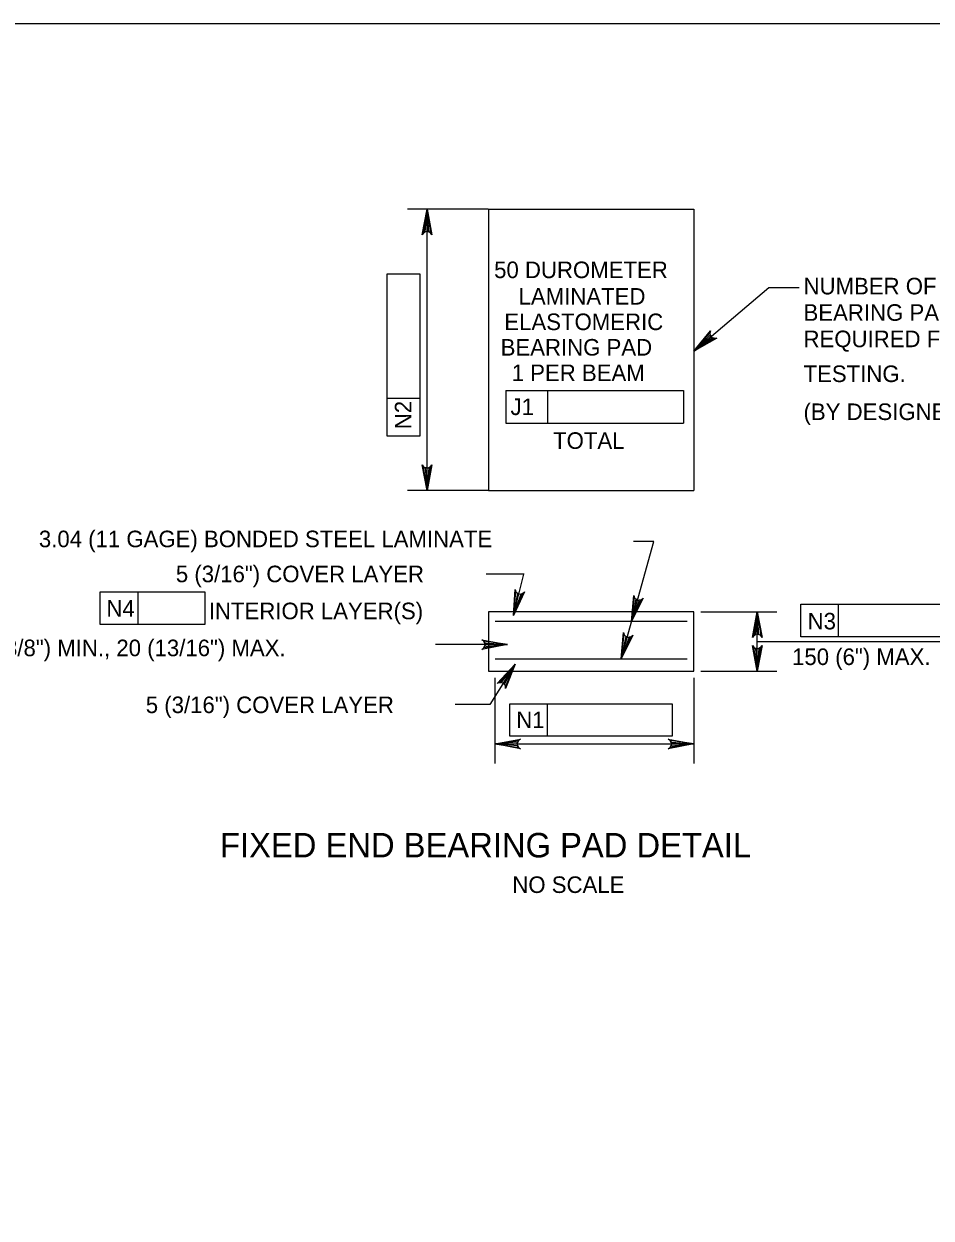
# Model space of a CAD drawing. Extents: x -13 to 81, y -176 to 0.
# Drawn here: x 52.67 to 59.23, y -31.4 to -22.75 of the extents above; entities that cross this region are included whole.
import ezdxf

# ---------------------------------------------------------------- set-up
doc = ezdxf.new("R2010")
doc.units = 0
for name, color, linetype in [('Level 1', 7, 'Continuous'), ('Level 3', 7, 'Continuous'), ('Level 5', 7, 'Continuous'), ('Level 6', 7, 'Continuous'), ('Level 8', 7, 'Continuous')]:
    doc.layers.add(name, color=color, linetype=linetype)

msp = doc.modelspace()

# ---------------------------------------------------------------- linework, layer by layer
at = {"layer": 'Level 1'}
msp.add_lwpolyline([(35.75, -43.25), (67.25, -43.25), (67.25, -22.75), (35.75, -22.75)], close=True, dxfattribs=at)
at = {"layer": 'Level 3'}
for p, q in [((55.5849, -26.1297), (55.5849, -24.0916)), ((56.029, -24.0916), (57.5171, -24.0916)), ((56.029, -24.0916), (56.029, -26.1297)), ((57.5171, -24.0916), (57.5171, -26.1297)), ((55.2975, -24.5611), (55.5337, -24.5611)), ((55.2975, -25.4631), (55.2975, -24.5611)), ((55.5337, -24.5611), (55.5337, -25.7369)), ((58.0596, -24.6599), (58.2797, -24.6599)), ((56.1547, -25.4057), (56.4571, -25.4057)), ((56.1547, -25.4057), (56.1547, -25.6419)), ((56.4571, -25.4057), (56.4571, -25.6419)), ((56.4571, -25.4057), (57.4407, -25.4057)), ((57.4407, -25.4057), (57.4407, -25.6419)), ((55.2975, -25.7369), (55.2975, -25.4631)), ((55.5337, -25.4631), (55.2975, -25.4631)), ((56.1547, -25.6419), (57.4407, -25.6419)), ((55.5337, -25.7369), (55.2975, -25.7369)), ((56.029, -26.1297), (57.5171, -26.1297)), ((56.2869, -26.7374), (56.0134, -26.7374)), ((56.2097, -27.037), (56.2868, -26.7373)), ((53.2192, -27.1005), (53.2192, -26.8643)), ((53.2192, -26.8643), (53.9756, -26.8643)), ((53.493, -27.1005), (53.493, -26.8643)), ((53.9756, -26.8643), (53.9756, -27.1005)), ((58.2901, -26.9548), (58.5639, -26.9548)), ((58.2901, -27.1909), (58.2901, -26.9548)), ((58.5639, -27.1909), (58.5639, -26.9548)), ((58.5639, -26.9548), (59.4659, -26.9548)), ((57.5171, -27.0092), (56.029, -27.0092)), ((56.029, -27.0092), (56.029, -27.4384)), ((57.5171, -27.4384), (57.5171, -27.0092)), ((57.5662, -27.0092), (58.1169, -27.0092)), ((57.9752, -27.4384), (57.9752, -27.0092)), ((57.9752, -27.0092), (57.9752, -27.0092)), ((53.9756, -27.1005), (53.2192, -27.1005)), ((57.4671, -27.0803), (56.079, -27.0803)), ((57.9752, -27.2237), (59.4815, -27.2237)), ((59.4659, -27.1909), (58.2901, -27.1909)), ((56.2222, -27.3879), (56.0384, -27.6814)), ((56.079, -27.349), (57.4671, -27.349)), ((56.029, -27.4384), (57.5171, -27.4384)), ((57.5662, -27.4384), (58.1169, -27.4384)), ((56.0384, -27.6814), (55.7892, -27.6814)), ((56.1831, -27.6747), (56.4569, -27.6747)), ((56.1831, -27.911), (56.1831, -27.6747)), ((56.4569, -27.911), (56.4569, -27.6747)), ((56.4569, -27.6747), (57.3588, -27.6747)), ((57.3588, -27.6747), (57.3588, -27.911)), ((57.3588, -27.911), (56.1831, -27.911))]:
    msp.add_line(p, q, dxfattribs=at)
for points in [[(55.5849, -24.0916), (55.6198, -24.278), (55.6099, -24.2637), (55.5974, -24.2562), (55.5849, -24.2541), (55.5724, -24.2562), (55.5599, -24.2637), (55.55, -24.278), (55.5849, -24.0916), (55.5599, -24.2637), (55.5724, -24.2562), (55.5849, -24.0916), (55.5849, -24.2541), (55.5974, -24.2562), (55.5849, -24.0916), (55.6099, -24.2637)], [(57.5171, -25.1202), (58.0596, -24.6598)], [(57.5171, -25.1202), (57.6366, -24.9729), (57.6321, -24.9898), (57.6345, -25.0041), (57.641, -25.015), (57.6507, -25.0232), (57.6644, -25.0279), (57.6818, -25.0262), (57.5171, -25.1202), (57.6644, -25.0279), (57.6507, -25.0232), (57.5171, -25.1202), (57.641, -25.015), (57.6345, -25.0041), (57.5171, -25.1202), (57.6321, -24.9898)], [(55.5849, -26.1297), (55.55, -25.9433), (55.5599, -25.9577), (55.5724, -25.9651), (55.5849, -25.9672), (55.5974, -25.9651), (55.6099, -25.9577), (55.6198, -25.9433), (55.5849, -26.1297), (55.6099, -25.9577), (55.5974, -25.9651), (55.5849, -26.1297), (55.5849, -25.9672), (55.5724, -25.9651), (55.5849, -26.1297), (55.5599, -25.9577)], [(56.2097, -27.037), (56.2223, -26.8477), (56.2284, -26.8642), (56.2387, -26.8744), (56.2503, -26.8796), (56.2628, -26.8807), (56.2768, -26.8766), (56.29, -26.8652), (56.2097, -27.037), (56.2768, -26.8766), (56.2628, -26.8807), (56.2097, -27.037), (56.2503, -26.8796), (56.2387, -26.8744), (56.2097, -27.037), (56.2284, -26.8642)], [(57.0656, -27.0803), (57.0816, -26.8913), (57.0873, -26.9078), (57.0974, -26.9183), (57.1089, -26.9237), (57.1215, -26.925), (57.1355, -26.9212), (57.1489, -26.91), (57.0656, -27.0803), (57.1355, -26.9212), (57.1215, -26.925), (57.0656, -27.0803), (57.1089, -26.9237), (57.0974, -26.9183), (57.0656, -27.0803), (57.0873, -26.9078)], [(57.9752, -27.0092), (58.0102, -27.1956), (58.0003, -27.1812), (57.9877, -27.1738), (57.9752, -27.1717), (57.9627, -27.1738), (57.9502, -27.1812), (57.9403, -27.1956), (57.9752, -27.0092), (57.9502, -27.1812), (57.9627, -27.1738), (57.9752, -27.0092), (57.9752, -27.1717), (57.9877, -27.1738), (57.9752, -27.0092), (58.0003, -27.1812)], [(56.9912, -27.349), (57.0072, -27.16), (57.013, -27.1765), (57.0231, -27.187), (57.0346, -27.1924), (57.0472, -27.1937), (57.0612, -27.1898), (57.0746, -27.1787), (56.9912, -27.349), (57.0612, -27.1898), (57.0472, -27.1937), (56.9912, -27.349), (57.0346, -27.1924), (57.0231, -27.187), (56.9912, -27.349), (57.013, -27.1765)], [(56.1679, -27.246), (55.9815, -27.2809), (55.9958, -27.271), (56.0033, -27.2585), (56.0054, -27.246), (56.0033, -27.2335), (55.9958, -27.221), (55.9815, -27.2111), (56.1679, -27.246), (55.9958, -27.221), (56.0033, -27.2335), (56.1679, -27.246), (56.0054, -27.246), (56.0033, -27.2585), (56.1679, -27.246), (55.9958, -27.271)], [(57.9752, -27.4384), (57.9403, -27.252), (57.9502, -27.2663), (57.9627, -27.2737), (57.9752, -27.2759), (57.9877, -27.2737), (58.0003, -27.2663), (58.0102, -27.252), (57.9752, -27.4384), (58.0003, -27.2663), (57.9877, -27.2737), (57.9752, -27.4384), (57.9752, -27.2759), (57.9627, -27.2737), (57.9752, -27.4384), (57.9502, -27.2663)], [(56.2222, -27.3879), (56.1528, -27.5645), (56.1521, -27.547), (56.1454, -27.5341), (56.1359, -27.5257), (56.1242, -27.5208), (56.1097, -27.5205), (56.0936, -27.5273), (56.2222, -27.3879), (56.1097, -27.5205), (56.1242, -27.5208), (56.2222, -27.3879), (56.1359, -27.5257), (56.1454, -27.5341), (56.2222, -27.3879), (56.1521, -27.547)], [(56.0758, -27.9664), (56.2623, -27.9315), (56.2479, -27.9414), (56.2405, -27.9539), (56.2383, -27.9664), (56.2405, -27.9789), (56.2479, -27.9914), (56.2623, -28.0013), (56.0758, -27.9664), (56.2479, -27.9914), (56.2405, -27.9789), (56.0758, -27.9664), (56.2383, -27.9664), (56.2405, -27.9539), (56.0758, -27.9664), (56.2479, -27.9414)], [(57.5171, -27.9664), (57.3307, -28.0013), (57.345, -27.9914), (57.3524, -27.9789), (57.3546, -27.9664), (57.3524, -27.9539), (57.345, -27.9414), (57.3307, -27.9315), (57.5171, -27.9664), (57.345, -27.9414), (57.3524, -27.9539), (57.5171, -27.9664), (57.3546, -27.9664), (57.3524, -27.9789), (57.5171, -27.9664), (57.345, -27.9914)]]:
    msp.add_lwpolyline(points, dxfattribs=at)
at = {"layer": 'Level 5'}
for p, q in [((56.993, -27.3425), (57.2262, -26.4999)), ((56.1679, -27.246), (55.645, -27.246))]:
    msp.add_line(p, q, dxfattribs=at)
at = {"layer": 'Level 6'}
msp.add_line((57.2262, -26.4999), (57.0788, -26.4999), dxfattribs=at)
at = {"layer": 'Level 8'}
for p, q in [((56.0266, -24.0916), (55.4432, -24.0916)), ((56.0266, -26.1297), (55.4432, -26.1297)), ((56.0758, -27.4876), (56.0758, -28.1081)), ((57.5171, -27.4876), (57.5171, -28.1081)), ((56.0758, -27.9664), (57.5171, -27.9664))]:
    msp.add_line(p, q, dxfattribs=at)
for points in [[(55.5692, -24.1861), (55.6006, -24.1861), (55.5849, -24.0916)], [(55.5692, -26.0352), (55.6006, -26.0352), (55.5849, -26.1297)]]:
    msp.add_lwpolyline(points, close=True, dxfattribs=at)

# ---------------------------------------------------------------- texts
at = {"layer": 'Level 3'}
for s, height, p in [('50 DUROMETER', 0.12, (56.0706, -24.5917)), ('NUMBER OF', 0.12, (58.3103, -24.7096)), ('LAMINATED', 0.12, (56.2476, -24.7838)), ('BEARING PADS', 0.12, (58.3103, -24.9009)), ('ELASTOMERIC', 0.12, (56.1444, -24.9684)), ('REQUIRED FOR', 0.12, (58.3103, -25.0921)), ('BEARING PAD', 0.12, (56.1177, -25.153)), ('1 PER BEAM', 0.12, (56.1978, -25.3377)), ('TESTING.', 0.12, (58.3103, -25.3447)), ('(BY DESIGNER)', 0.12, (58.3103, -25.6197)), ('TOTAL', 0.12, (56.4973, -25.8287)), ('3.04 (11 GAGE) BONDED STEEL LAMINATE', 0.12, (52.7751, -26.5412)), ('5 (3/16") COVER LAYER', 0.12, (53.7667, -26.7948)), ('N4', 0.12, (53.2642, -27.0443)), ('INTERIOR LAYER(S)', 0.12, (54.0051, -27.0628)), ('N3', 0.12, (58.3399, -27.1367)), ('10 (3/8") MIN., 20 (13/16") MAX.', 0.12, (52.2535, -27.3306)), ('150 (6") MAX.', 0.12, (58.2273, -27.3946)), ('5 (3/16") COVER LAYER', 0.12, (53.549, -27.7429)), ('N1', 0.12, (56.2306, -27.8516)), ('FIXED END BEARING PAD DETAIL', 0.177167, (54.0865, -28.7882)), ('NO SCALE', 0.12, (56.2024, -29.0458))]:
    msp.add_text(s, height=height, dxfattribs=at).set_placement(p)
for s, rotation, p in [('N2', 90, (55.4721, -25.686)), ('J1', 359.93823, (56.1894, -25.5837))]:
    msp.add_text(s, height=0.12, rotation=rotation, dxfattribs=at).set_placement(p)

doc.saveas('drawing.dxf')
